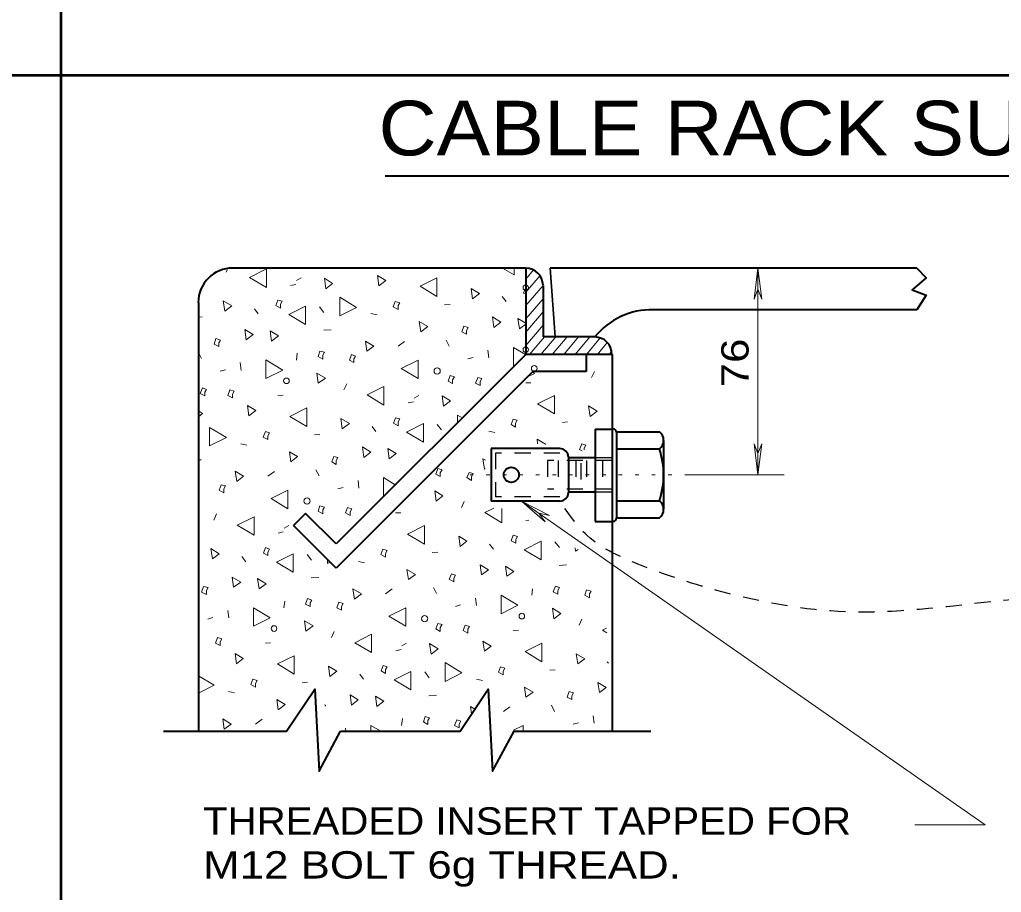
# Model space of a CAD drawing. Extents: x 312583 to 312854, y 144419 to 144597.
# Drawn here: x 312751.27 to 312778.57, y 144463.44 to 144487.71 of the extents above; entities that cross this region are included whole.
import ezdxf
from ezdxf.enums import TextEntityAlignment as Align

# ---------------------------------------------------------------- set-up
doc = ezdxf.new("R2010")
doc.units = 0
doc.header["$LTSCALE"] = 0.3
doc.header["$PDMODE"] = 32
doc.header["$PDSIZE"] = 0.15
doc.linetypes.add('DOTTED', pattern=[1.5, 0.3, -1.2])
doc.linetypes.add('SHORT_DASHED', pattern=[2.7, 1.5, -1.2])
doc.layers.add('1', color=7, linetype='Continuous', lineweight=13)

msp = doc.modelspace()

# ---------------------------------------------------------------- linework, layer by layer
at = {"layer": '1', "lineweight": 53}
for p, q in [((312752.4335, 144432.4767), (312752.4335, 144510.2401)), ((312796.3473, 144486.1644), (312693.5008, 144486.1644))]:
    msp.add_line(p, q, dxfattribs=at)
at = {"layer": '1', "lineweight": 40}
for p, q in [((312761.435, 144483.3724), (312788.6989, 144483.3724)), ((312765.3433, 144480.8054), (312757.2013, 144480.8054)), ((312765.3433, 144480.8054), (312765.3433, 144478.4058)), ((312776.2146, 144480.8054), (312766.0256, 144480.8054)), ((312765.8263, 144480.3224), (312765.8263, 144478.8888)), ((312756.2429, 144479.8471), (312756.2429, 144467.9254)), ((312776.2146, 144479.6478), (312768.8929, 144479.6478)), ((312767.2599, 144478.8888), (312765.8263, 144478.8888)), ((312765.3433, 144478.4058), (312760.0763, 144473.1388)), ((312767.7429, 144478.4058), (312765.3433, 144478.4058)), ((312767.0223, 144478.4058), (312767.0223, 144477.9304)), ((312767.7429, 144478.4058), (312767.7429, 144467.9254)), ((312765.5426, 144477.9304), (312760.0763, 144472.4564)), ((312767.0223, 144477.9304), (312765.5426, 144477.9304)), ((312767.2753, 144476.3281), (312767.7736, 144476.3281)), ((312767.2753, 144476.3281), (312767.2753, 144473.7598)), ((312767.8656, 144476.2514), (312769.0616, 144476.2514)), ((312767.8656, 144476.2361), (312767.8656, 144473.8594)), ((312769.1766, 144476.0138), (312769.1766, 144474.0971)), ((312764.3849, 144475.7838), (312764.3849, 144474.3271)), ((312766.2939, 144475.7838), (312764.3849, 144475.7838)), ((312766.5316, 144475.5461), (312766.5316, 144474.5648)), ((312767.8656, 144475.7761), (312769.0616, 144475.7761)), ((312767.2753, 144475.5308), (312766.5316, 144475.5308)), ((312767.2753, 144474.5724), (312766.5316, 144474.5724)), ((312766.2939, 144474.3271), (312764.3849, 144474.3271)), ((312767.8656, 144474.3348), (312769.0616, 144474.3348)), ((312759.2253, 144473.9821), (312758.8879, 144473.6448)), ((312760.0763, 144473.1388), (312759.2253, 144473.9821)), ((312760.0763, 144472.4564), (312758.8879, 144473.6448)), ((312767.2753, 144473.7598), (312767.7736, 144473.7598)), ((312767.8656, 144473.8594), (312769.0616, 144473.8594)), ((312755.2769, 144467.9254), (312758.6963, 144467.9254))]:
    msp.add_line(p, q, dxfattribs=at)
at = {"layer": '1'}
for p, q in [((312757.0479, 144480.7518), (312757.0173, 144480.6904)), ((312764.6993, 144480.8054), (312765.0213, 144480.6138)), ((312765.0213, 144480.6138), (312765.0213, 144480.8054)), ((312765.5579, 144480.7518), (312765.3433, 144480.4988)), ((312771.7986, 144480.8054), (312771.6913, 144479.9391)), ((312771.7986, 144475.0554), (312771.7986, 144480.8054)), ((312771.7986, 144480.8054), (312771.9059, 144479.9391)), ((312758.9723, 144480.4604), (312759.1026, 144480.5294)), ((312765.7419, 144480.5984), (312765.3433, 144480.1308)), ((312758.8036, 144480.3224), (312758.9493, 144480.3531)), ((312765.8263, 144480.3224), (312765.3433, 144479.7628)), ((312771.6913, 144479.9391), (312771.7986, 144480.2151)), ((312771.9059, 144479.9391), (312771.7986, 144480.2151)), ((312764.6916, 144480.0158), (312764.7989, 144479.8778)), ((312765.8263, 144479.9544), (312765.3433, 144479.3948)), ((312757.7993, 144479.6708), (312757.9066, 144479.5328)), ((312759.6086, 144479.7321), (312759.7313, 144479.5711)), ((312763.0893, 144479.7858), (312763.2426, 144479.7934)), ((312756.2429, 144479.4408), (312756.3503, 144479.4484)), ((312761.0423, 144479.5404), (312761.2109, 144479.5021)), ((312765.8263, 144479.5864), (312765.3433, 144479.0268)), ((312765.1669, 144479.1188), (312765.3433, 144479.2491)), ((312765.8263, 144479.2184), (312765.3433, 144478.6511)), ((312759.7313, 144479.0804), (312759.9383, 144479.0881)), ((312765.8646, 144478.8888), (312765.4506, 144478.4058)), ((312766.1789, 144478.8888), (312765.7649, 144478.4058)), ((312766.4933, 144478.8888), (312766.0793, 144478.4058)), ((312766.8076, 144478.8888), (312766.4013, 144478.4058)), ((312767.1219, 144478.8888), (312766.7156, 144478.4058)), ((312767.4133, 144478.8658), (312767.0299, 144478.4058)), ((312761.9776, 144478.7661), (312761.7936, 144478.6358)), ((312763.1276, 144478.8044), (312763.2196, 144478.6358)), ((312765.3356, 144478.3981), (312765.0059, 144478.5974)), ((312767.6126, 144478.7354), (312767.3366, 144478.4058)), ((312758.9723, 144478.2448), (312758.9876, 144478.4364)), ((312763.7333, 144478.2831), (312763.8866, 144478.3214)), ((312764.2929, 144478.5208), (312764.3159, 144478.3061)), ((312767.7353, 144478.4978), (312767.6509, 144478.4058)), ((312757.4083, 144478.1758), (312757.4313, 144477.9611)), ((312756.8486, 144477.9381), (312756.9943, 144477.9764)), ((312767.2523, 144477.9304), (312767.1756, 144477.7618)), ((312760.3676, 144477.5854), (312760.2909, 144477.4168)), ((312765.3433, 144477.6161), (312765.4889, 144477.6161)), ((312758.4509, 144477.2634), (312758.5966, 144477.2711)), ((312762.2459, 144477.1868), (312762.3763, 144477.2634)), ((312762.0773, 144477.0564), (312762.2229, 144477.0871)), ((312763.4496, 144476.7191), (312763.4496, 144476.5121)), ((312763.5799, 144476.6424), (312763.4496, 144476.7191)), ((312761.0729, 144476.3971), (312761.1803, 144476.2591)), ((312762.8823, 144476.4584), (312763.0049, 144476.3051)), ((312766.3629, 144476.5121), (312766.5086, 144476.5274)), ((312759.4706, 144476.1671), (312759.6239, 144476.1748)), ((312764.3159, 144476.2668), (312764.4846, 144476.2284)), ((312757.4236, 144475.9218), (312757.5923, 144475.8834)), ((312771.6913, 144475.9218), (312771.7986, 144475.6458)), ((312771.7986, 144475.0554), (312771.6913, 144475.9218)), ((312771.9059, 144475.9218), (312771.7986, 144475.6458)), ((312771.7986, 144475.0554), (312771.9059, 144475.9218)), ((312766.9686, 144475.7531), (312766.9686, 144475.7991)), ((312756.2429, 144475.4694), (312756.3196, 144475.4694)), ((312758.3589, 144475.1474), (312758.1749, 144475.0171)), ((312759.5089, 144475.1934), (312759.6009, 144475.0248)), ((312764.2009, 144475.2164), (312764.2163, 144475.2318)), ((312769.8666, 144475.0554), (312772.5269, 144475.0554)), ((312760.6819, 144474.9021), (312760.7049, 144474.6874)), ((312761.7169, 144474.7794), (312761.3873, 144474.9788)), ((312760.1223, 144474.6644), (312760.2679, 144474.7028)), ((312763.6336, 144474.3118), (312763.5569, 144474.1431)), ((312778.1159, 144465.3188), (312765.2283, 144474.3271)), ((312765.2283, 144474.3271), (312765.8799, 144473.7444)), ((312765.2283, 144474.3271), (312766.0026, 144473.9208)), ((312756.7489, 144473.9668), (312756.6723, 144473.7981)), ((312761.7246, 144473.9974), (312761.8703, 144473.9974)), ((312764.6763, 144473.7214), (312764.6763, 144474.1201)), ((312765.8799, 144473.7444), (312765.7113, 144473.9898)), ((312766.0026, 144473.9208), (312765.7113, 144473.9898)), ((312758.6273, 144473.5758), (312758.7576, 144473.6448)), ((312765.3509, 144473.7828), (312765.4276, 144473.7981)), ((312758.4586, 144473.4378), (312758.6043, 144473.4684)), ((312764.3389, 144473.1311), (312764.4463, 144472.9931)), ((312766.1559, 144473.1924), (312766.2786, 144473.0314)), ((312759.2636, 144472.8398), (312759.3863, 144472.6864)), ((312762.7443, 144472.8934), (312762.8976, 144472.9088)), ((312757.4543, 144472.7861), (312757.5616, 144472.6404)), ((312760.6973, 144472.6481), (312760.8659, 144472.6098)), ((312766.2709, 144472.5331), (312766.4779, 144472.5484)), ((312759.3786, 144472.1881), (312759.5933, 144472.2034)), ((312761.6326, 144471.8814), (312761.4486, 144471.7434)), ((312762.7826, 144471.9198), (312762.8669, 144471.7511)), ((312765.5119, 144471.7051), (312765.5349, 144471.8891)), ((312758.6196, 144471.3601), (312758.6426, 144471.5441)), ((312763.9479, 144471.6284), (312763.9709, 144471.4214)), ((312757.0633, 144471.2834), (312757.0863, 144471.0764)), ((312763.3883, 144471.3908), (312763.5339, 144471.4368)), ((312756.5036, 144471.0458), (312756.6493, 144471.0918)), ((312766.9073, 144471.0458), (312766.8306, 144470.8771)), ((312760.0226, 144470.7008), (312759.9459, 144470.5321)), ((312764.9983, 144470.7238), (312765.1439, 144470.7314)), ((312758.1059, 144470.3788), (312758.2516, 144470.3864)), ((312761.9009, 144470.3021), (312762.0313, 144470.3711)), ((312761.7323, 144470.1641), (312761.8779, 144470.1948)), ((312767.6126, 144469.8574), (312767.6433, 144469.8191)), ((312762.5373, 144469.5738), (312762.6599, 144469.4128)), ((312766.0103, 144469.6198), (312766.1636, 144469.6351)), ((312759.1256, 144469.2748), (312759.2789, 144469.2901)), ((312760.7279, 144469.5124), (312760.8353, 144469.3744)), ((312763.9709, 144469.3744), (312764.1396, 144469.3361)), ((312757.0786, 144469.0294), (312757.2473, 144468.9911)), ((312762.6523, 144468.9144), (312762.8669, 144468.9298)), ((312764.9063, 144468.6078), (312764.7223, 144468.4698)), ((312766.0563, 144468.6461), (312766.1406, 144468.4774)), ((312758.0139, 144468.2628), (312757.8299, 144468.1248)), ((312761.8933, 144468.0864), (312761.9163, 144468.2781)), ((312767.2216, 144468.3548), (312767.2446, 144468.1478)), ((312760.3369, 144468.0098), (312760.3446, 144467.9254)), ((312761.0423, 144468.0864), (312761.0423, 144467.9254)), ((312761.3183, 144467.9254), (312761.0423, 144468.0864)), ((312766.6619, 144468.1248), (312766.8076, 144468.1631)), ((312778.1159, 144465.3188), (312776.1609, 144465.3188))]:
    msp.add_line(p, q, dxfattribs=at)
at = {"layer": '1', "lineweight": 35}
msp.add_line((312766.1636, 144478.8888), (312766.0256, 144480.8054), dxfattribs=at)
at = {"layer": '1', "linetype": 'SHORT_DASHED', "lineweight": 25}
for p, q in [((312765.9489, 144475.4541), (312765.9489, 144474.6568)), ((312767.7429, 144475.4541), (312765.9489, 144475.4541)), ((312766.2479, 144475.4541), (312766.2479, 144474.6568)), ((312766.7386, 144475.4541), (312766.7386, 144474.6568)), ((312766.8766, 144475.3774), (312766.8766, 144474.7334)), ((312767.0299, 144475.4541), (312767.0299, 144474.6568)), ((312767.7429, 144475.5308), (312767.2753, 144475.5308)), ((312767.4746, 144475.4541), (312767.4746, 144474.6568)), ((312767.7429, 144474.6568), (312765.9489, 144474.6568)), ((312767.7429, 144474.5724), (312767.2753, 144474.5724)), ((312766.2939, 144474.4421), (312764.5076, 144474.4421))]:
    msp.add_line(p, q, dxfattribs=at)
at = {"layer": '1', "linetype": 'DOTTED'}
msp.add_line((312769.8666, 144475.0554), (312763.8023, 144475.0554), dxfattribs=at)
at = {"layer": '1'}
for points in [[(312758.1366, 144480.2688), (312758.1366, 144480.7824), (312757.6689, 144480.5448)], [(312759.7849, 144480.2304), (312759.9766, 144480.3761), (312759.7466, 144480.5218)], [(312761.2646, 144480.3071), (312761.4563, 144480.4604), (312761.2263, 144480.5984)], [(312762.8746, 144480.0158), (312762.8746, 144480.5294), (312762.4069, 144480.2994)], [(312763.8636, 144479.9544), (312764.0553, 144480.1001), (312763.8253, 144480.2381)], [(312758.5276, 144479.8011), (312758.5736, 144479.8854), (312758.4509, 144479.9161), (312758.3973, 144479.7628), (312758.5276, 144479.6938)], [(312760.1759, 144479.9928), (312760.1759, 144479.4791), (312760.6436, 144479.7091)], [(312756.9789, 144479.6094), (312757.1706, 144479.7551), (312756.9329, 144479.8931)], [(312759.2253, 144479.2338), (312759.2253, 144479.7474), (312758.7576, 144479.5174)], [(312761.7936, 144479.7628), (312761.8396, 144479.8394), (312761.7169, 144479.8778), (312761.6633, 144479.7244), (312761.7936, 144479.6554)], [(312764.4616, 144479.1571), (312764.6533, 144479.3028), (312764.4233, 144479.4484)], [(312757.5693, 144478.8121), (312757.7686, 144478.9578), (312757.5309, 144479.0958)], [(312762.4299, 144479.0344), (312762.6216, 144479.1801), (312762.3839, 144479.3181)], [(312763.6949, 144479.0728), (312763.7409, 144479.1571), (312763.6259, 144479.1878), (312763.5646, 144479.0344), (312763.6949, 144478.9654)], [(312756.8103, 144478.7278), (312756.8563, 144478.8044), (312756.7336, 144478.8428), (312756.6799, 144478.6894), (312756.8103, 144478.6204)], [(312758.2746, 144478.7738), (312758.4739, 144478.9194), (312758.2363, 144479.0574)], [(312760.9273, 144478.4901), (312761.1189, 144478.6358), (312760.8889, 144478.7738)], [(312759.7006, 144478.3828), (312759.7466, 144478.4671), (312759.6239, 144478.4978), (312759.5703, 144478.3444), (312759.7006, 144478.2754)], [(312760.5669, 144478.2831), (312760.6129, 144478.3598), (312760.4979, 144478.3981), (312760.4443, 144478.2448), (312760.5669, 144478.1758)], [(312758.1213, 144478.2524), (312758.1213, 144477.7311), (312758.5889, 144477.9688)], [(312762.3533, 144477.7311), (312762.3533, 144478.2448), (312761.8856, 144478.0148)], [(312759.5779, 144477.6008), (312759.7773, 144477.7464), (312759.5396, 144477.8844)], [(312763.3116, 144477.7004), (312763.3653, 144477.7771), (312763.2426, 144477.8154), (312763.1889, 144477.6621), (312763.3116, 144477.5931)], [(312764.0783, 144477.6468), (312764.1243, 144477.7311), (312764.0093, 144477.7618), (312763.9479, 144477.6084), (312764.0783, 144477.5394)], [(312756.4269, 144477.3554), (312756.4729, 144477.4321), (312756.3579, 144477.4704), (312756.2966, 144477.3171), (312756.4269, 144477.2481)], [(312761.4026, 144476.9951), (312761.4026, 144477.5088), (312760.9349, 144477.2788)], [(312757.1936, 144477.3018), (312757.2396, 144477.3784), (312757.1169, 144477.4168), (312757.0633, 144477.2634), (312757.1936, 144477.1944)], [(312763.0586, 144476.9644), (312763.2503, 144477.1101), (312763.0203, 144477.2481)], [(312766.1406, 144476.7498), (312766.1406, 144477.2634), (312765.6729, 144477.0258)], [(312757.6459, 144476.6961), (312757.8376, 144476.8418), (312757.6076, 144476.9798)], [(312759.2559, 144476.3971), (312759.2559, 144476.9184), (312758.7883, 144476.6808)], [(312767.1373, 144476.6808), (312767.3289, 144476.8264), (312767.0913, 144476.9721)], [(312761.7936, 144476.5274), (312761.8396, 144476.6118), (312761.7246, 144476.6424), (312761.6709, 144476.4968), (312761.7936, 144476.4201)], [(312756.5573, 144476.3741), (312756.5573, 144475.8604), (312757.0249, 144476.0904)], [(312760.2449, 144476.3358), (312760.4443, 144476.4814), (312760.2066, 144476.6194)], [(312762.4989, 144475.9601), (312762.4989, 144476.4814), (312762.0313, 144476.2438)], [(312765.0596, 144476.4891), (312765.1056, 144476.5734), (312764.9906, 144476.6041), (312764.9369, 144476.4584), (312765.0596, 144476.3818)], [(312758.1749, 144476.1441), (312758.2209, 144476.2208), (312758.1059, 144476.2591), (312758.0446, 144476.1058), (312758.1749, 144476.0368)], [(312760.8429, 144475.5384), (312761.0346, 144475.6841), (312760.8046, 144475.8298)], [(312758.8113, 144475.4158), (312759.0029, 144475.5614), (312758.7729, 144475.6994)], [(312760.0763, 144475.4541), (312760.1223, 144475.5384), (312760.0073, 144475.5691), (312759.9536, 144475.4158), (312760.0763, 144475.3468)], [(312761.5483, 144475.5001), (312761.7399, 144475.6458), (312761.5099, 144475.7914)], [(312757.3086, 144474.8714), (312757.5003, 144475.0171), (312757.2703, 144475.1551)], [(312762.9666, 144475.1091), (312763.0203, 144475.1934), (312762.8976, 144475.2318), (312762.8439, 144475.0784), (312762.9666, 144475.0094)], [(312763.8406, 144475.0094), (312763.8866, 144475.0938), (312763.7716, 144475.1244), (312763.7103, 144474.9788), (312763.8406, 144474.9021)], [(312756.9483, 144474.6644), (312757.0019, 144474.7488), (312756.8793, 144474.7794), (312756.8256, 144474.6338), (312756.9483, 144474.5571)], [(312758.7346, 144474.1124), (312758.7346, 144474.6338), (312758.2669, 144474.3961)], [(312762.8516, 144474.3271), (312763.0433, 144474.4728), (312762.8133, 144474.6108)], [(312759.7006, 144474.0818), (312759.7466, 144474.1584), (312759.6239, 144474.1968), (312759.5703, 144474.0434), (312759.7006, 144473.9744)], [(312760.4596, 144474.0281), (312760.5133, 144474.1124), (312760.3906, 144474.1431), (312760.3369, 144473.9974), (312760.4596, 144473.9208)], [(312757.7916, 144473.3764), (312757.7916, 144473.8901), (312757.3239, 144473.6601)], [(312762.5296, 144473.1311), (312762.5296, 144473.6448), (312762.0619, 144473.4071)], [(312765.0673, 144473.2614), (312765.1133, 144473.3381), (312764.9983, 144473.3764), (312764.9369, 144473.2231), (312765.0673, 144473.1541)], [(312763.5186, 144473.0621), (312763.7103, 144473.2154), (312763.4803, 144473.3534)], [(312765.7726, 144472.6941), (312765.7726, 144473.2078), (312765.3049, 144472.9701)], [(312756.6339, 144472.7171), (312756.8256, 144472.8628), (312756.5879, 144473.0084)], [(312758.1749, 144472.9088), (312758.2209, 144472.9931), (312758.1059, 144473.0314), (312758.0523, 144472.8781), (312758.1749, 144472.8091)], [(312758.8803, 144472.3491), (312758.8803, 144472.8628), (312758.4126, 144472.6251)], [(312761.4486, 144472.8704), (312761.4946, 144472.9548), (312761.3719, 144472.9854), (312761.3183, 144472.8398), (312761.4486, 144472.7631)], [(312764.1166, 144472.2724), (312764.3083, 144472.4181), (312764.0783, 144472.5561)], [(312762.0849, 144472.1421), (312762.2766, 144472.2878), (312762.0389, 144472.4258)], [(312763.3499, 144472.1804), (312763.3959, 144472.2648), (312763.2809, 144472.3031), (312763.2196, 144472.1498), (312763.3499, 144472.0808)], [(312764.8219, 144472.2341), (312765.0136, 144472.3721), (312764.7836, 144472.5178)], [(312757.2243, 144471.9274), (312757.4236, 144472.0731), (312757.1859, 144472.2111)], [(312757.9296, 144471.8814), (312758.1289, 144472.0271), (312757.8913, 144472.1728)], [(312756.4653, 144471.8354), (312756.5113, 144471.9198), (312756.3886, 144471.9504), (312756.3349, 144471.7971), (312756.4653, 144471.7281)], [(312760.5823, 144471.5978), (312760.7739, 144471.7434), (312760.5363, 144471.8814)], [(312766.2403, 144471.8431), (312766.2863, 144471.9198), (312766.1713, 144471.9581), (312766.1099, 144471.8048), (312766.2403, 144471.7358)], [(312767.1143, 144471.7434), (312767.1603, 144471.8201), (312767.0376, 144471.8584), (312766.9839, 144471.7051), (312767.1143, 144471.6361)], [(312759.3556, 144471.4981), (312759.4016, 144471.5748), (312759.2789, 144471.6131), (312759.2253, 144471.4598), (312759.3556, 144471.3908)], [(312760.2219, 144471.3908), (312760.2679, 144471.4751), (312760.1529, 144471.5134), (312760.0916, 144471.3601), (312760.2219, 144471.2911)], [(312764.6609, 144471.7051), (312764.6609, 144471.1914), (312765.1286, 144471.4291)], [(312757.7763, 144471.3601), (312757.7763, 144470.8464), (312758.2439, 144471.0764)], [(312762.0083, 144470.8464), (312762.0083, 144471.3601), (312761.5406, 144471.1224)], [(312766.1253, 144471.0534), (312766.3169, 144471.1991), (312766.0869, 144471.3448)], [(312759.2329, 144470.7084), (312759.4323, 144470.8541), (312759.1946, 144470.9921)], [(312762.9666, 144470.8081), (312763.0203, 144470.8924), (312762.8976, 144470.9231), (312762.8439, 144470.7698), (312762.9666, 144470.7008)], [(312763.7333, 144470.7621), (312763.7793, 144470.8388), (312763.6643, 144470.8771), (312763.6029, 144470.7238), (312763.7333, 144470.6548)], [(312756.8486, 144470.4094), (312756.8946, 144470.4938), (312756.7719, 144470.5321), (312756.7183, 144470.3788), (312756.8486, 144470.3098)], [(312761.0576, 144470.1104), (312761.0576, 144470.6241), (312760.5899, 144470.3864)], [(312762.7136, 144470.0721), (312762.9053, 144470.2178), (312762.6676, 144470.3634)], [(312764.1933, 144470.1488), (312764.3849, 144470.2944), (312764.1473, 144470.4324)], [(312765.7956, 144469.8574), (312765.7956, 144470.3711), (312765.3279, 144470.1411)], [(312757.3009, 144469.8038), (312757.4926, 144469.9494), (312757.2626, 144470.0874)], [(312758.9109, 144469.5124), (312758.9109, 144470.0261), (312758.4433, 144469.7961)], [(312763.1046, 144469.8344), (312763.1046, 144469.3131), (312763.5723, 144469.5508)], [(312766.7923, 144469.7961), (312766.9839, 144469.9418), (312766.7463, 144470.0798)], [(312759.8999, 144469.4511), (312760.0916, 144469.5968), (312759.8616, 144469.7348)], [(312761.4486, 144469.6428), (312761.4946, 144469.7194), (312761.3796, 144469.7578), (312761.3259, 144469.6044), (312761.4486, 144469.5354)], [(312762.1539, 144469.0754), (312762.1539, 144469.5891), (312761.6863, 144469.3514)], [(312764.7146, 144469.5968), (312764.7606, 144469.6811), (312764.6456, 144469.7194), (312764.5843, 144469.5661), (312764.7146, 144469.4971)], [(312757.8299, 144469.2518), (312757.8759, 144469.3361), (312757.7609, 144469.3744), (312757.6996, 144469.2211), (312757.8299, 144469.1521)], [(312767.3903, 144468.9988), (312767.5819, 144469.1444), (312767.3443, 144469.2824)], [(312765.3509, 144468.8684), (312765.5503, 144469.0141), (312765.3126, 144469.1521)], [(312766.6236, 144468.9144), (312766.6696, 144468.9911), (312766.5546, 144469.0294), (312766.4933, 144468.8761), (312766.6236, 144468.8071)], [(312758.4663, 144468.5234), (312758.6579, 144468.6691), (312758.4203, 144468.8071)], [(312760.4979, 144468.6538), (312760.6896, 144468.7994), (312760.4596, 144468.9374)], [(312761.2033, 144468.6154), (312761.3949, 144468.7611), (312761.1649, 144468.8991)], [(312756.9636, 144467.9791), (312757.1553, 144468.1248), (312756.9253, 144468.2704)], [(312762.6216, 144468.2244), (312762.6676, 144468.3011), (312762.5526, 144468.3394), (312762.4989, 144468.1861), (312762.6216, 144468.1171)], [(312763.4956, 144468.1248), (312763.5416, 144468.2014), (312763.4266, 144468.2398), (312763.3653, 144468.0864), (312763.4956, 144468.0174)]]:
    msp.add_lwpolyline(points, close=True, dxfattribs=at)
at = {"layer": '1', "lineweight": 40}
for points in [[(312776.2146, 144480.8054), (312776.4753, 144480.5371), (312776.0843, 144480.1998), (312776.4753, 144480.0541), (312776.2146, 144479.6478)], [(312758.6963, 144467.9254), (312759.4783, 144469.0908), (312759.6009, 144466.8138), (312760.1989, 144467.9254)], [(312760.1989, 144467.9254), (312763.5186, 144467.9254), (312764.3006, 144469.0908), (312764.4233, 144466.8138), (312765.0213, 144467.9254), (312768.8239, 144467.9254)]]:
    msp.add_lwpolyline(points, dxfattribs=at)
at = {"layer": '1'}
for points in [[(312765.3433, 144480.2611), (312765.2819, 144480.1078), (312765.3433, 144480.0771)], [(312765.3433, 144479.2721), (312765.1286, 144479.4024), (312765.1669, 144479.1188)], [(312765.0059, 144478.5974), (312765.0059, 144478.0761), (312765.0213, 144478.0914)], [(312756.2429, 144478.4594), (312756.2429, 144478.4594), (312756.3273, 144478.2908)], [(312765.5349, 144477.9228), (312765.5886, 144477.8768), (312765.3969, 144477.7771)], [(312756.2429, 144476.6731), (312756.3579, 144476.7651), (312756.2429, 144476.8341)], [(312765.8876, 144475.8988), (312765.8953, 144475.9064), (312765.6576, 144476.0444), (312765.6729, 144475.9141)], [(312766.9686, 144475.7991), (312767.0146, 144475.8834), (312766.8996, 144475.9141), (312766.8383, 144475.7608), (312766.9149, 144475.7224)], [(312764.2239, 144475.4618), (312764.1549, 144475.5001), (312764.2009, 144475.2164)], [(312761.3873, 144474.9788), (312761.3873, 144474.4651), (312761.4103, 144474.4728)], [(312764.4539, 144474.1278), (312764.2086, 144474.0051), (312764.6763, 144473.7214)], [(312766.7156, 144473.0238), (312766.7233, 144472.9318), (312766.7999, 144472.9778)], [(312759.8309, 144472.7018), (312759.8309, 144472.5868), (312759.9076, 144472.6251)], [(312767.5896, 144470.7928), (312767.4823, 144470.7314), (312767.5973, 144470.6624)], [(312756.2429, 144468.9834), (312756.6799, 144469.2058), (312756.2429, 144469.4664)], [(312759.7696, 144468.6231), (312759.7773, 144468.6461), (312759.7466, 144468.6614)], [(312763.9326, 144468.5388), (312763.8099, 144468.6154), (312763.8406, 144468.4084)], [(312765.2743, 144467.9254), (312765.2743, 144468.0864), (312765.0059, 144467.9561)]]:
    msp.add_lwpolyline(points, dxfattribs=at)
at = {"layer": '1', "linetype": 'SHORT_DASHED', "lineweight": 25}
msp.add_lwpolyline([(312766.2939, 144475.6611), (312764.5076, 144475.6611), (312764.5076, 144474.4421)], dxfattribs=at)
at = {"layer": '1'}
for centre, radius in [((312762.8823, 144477.944), 0.0865), ((312765.5811, 144478.0151), 0.0784), ((312758.6922, 144477.6695), 0.0784), ((312759.265, 144474.3268), 0.0865), ((312765.2355, 144471.1261), 0.0784), ((312762.5367, 144471.0551), 0.0865), ((312758.3466, 144470.7805), 0.0784)]:
    msp.add_circle(centre, radius, dxfattribs=at)
at = {"layer": '1', "lineweight": 40}
msp.add_circle((312764.9427, 144475.0554), 0.2102, dxfattribs=at)
for centre, radius, start, end in [((312757.1994, 144479.8471), 0.9583, 90, 180), ((312765.3452, 144480.3263), 0.4792, 0, 90), ((312768.8444, 144477.6149), 2.0316, 88.63097, 141.1667), ((312767.2619, 144478.4096), 0.4792, 0, 90), ((312767.7717, 144476.2361), 0.0958, 0, 90), ((312768.8776, 144476.0138), 0.3009, 307.23717, 52.76282), ((312766.2901, 144475.5442), 0.2396, 0, 90), ((312766.9455, 144475.0554), 2.2331, 341.22405, 18.77595), ((312766.2901, 144474.5667), 0.2396, 270, 0), ((312768.8776, 144474.0971), 0.3009, 307.23718, 52.76283), ((312767.7717, 144473.8594), 0.0958, 270, 0)]:
    msp.add_arc(centre, radius, start, end, dxfattribs=at)
at = {"layer": '1', "linetype": 'SHORT_DASHED', "lineweight": 25}
msp.add_spline([(312784.5253, 144473.0314), (312782.4629, 144472.1958), (312778.3306, 144471.5288), (312774.2519, 144471.2451), (312770.7943, 144471.8048), (312768.5633, 144472.5331), (312767.0529, 144473.3688), (312766.2939, 144474.3271)], degree=3, dxfattribs=at)
at = {"layer": '1'}
for p in [(312765.3433, 144480.2611), (312765.3433, 144478.5361)]:
    msp.add_point(p, dxfattribs=at)

# ---------------------------------------------------------------- texts
at = {"layer": '1', "width": 1.1}
msp.add_text('CABLE RACK SUPPORTS', height=1.52, dxfattribs=at).set_placement((312774.7956, 144483.9389), align=Align.CENTER)
at = {"layer": '1', "width": 1.2}
msp.add_text('76 ', height=0.76, rotation=90, dxfattribs=at).set_placement((312771.5401, 144477.4883))
at = {"layer": '1'}
for s, width, p in [('THREADED INSERT TAPPED FOR', 1.1, (312756.3743, 144465.0494)), ('M12 BOLT 6g THREAD.', 1.2, (312756.3743, 144463.8294))]:
    msp.add_text(s, height=0.76, dxfattribs=dict(at, width=width)).set_placement(p)

doc.saveas('drawing.dxf')
